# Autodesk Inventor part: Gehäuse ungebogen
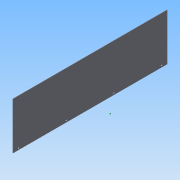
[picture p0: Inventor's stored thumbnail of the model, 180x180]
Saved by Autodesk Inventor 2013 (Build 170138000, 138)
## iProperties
Created: 2013-01
Part Number: Gehäuse ungebogen
Material: Allgemein
Document SubType Name: Modeling
Designer: Dan
Density: 1 g/cm^3
Author: Dan
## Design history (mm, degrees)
sketch "Skizze1"
  geometry: 1 further point
sketch "Skizze2"
  geometry: L1 (162.847, 43.02)-(-282.193, 43.02); L2 (-282.193, 43.02)-(-282.193, 179.02); L3 (-282.193, 179.02)-(162.847, 179.02); L4 (162.847, 179.02)-(162.847, 43.02); 1 further point
  constraints: 8 end point, 2 parallel, 1 horizontal, 1 perpendicular
  dimensions: "d0" = 445.04 distance of L2.end L3.end; "d2" = 136 distance of L1.end L2.end
extrude "Extrusion1" new body sketch "Skizze2" distance "d3" = 1; taper "d4" = 0 deg
hole "Bohrung1" diameter "d7" = 3.4; stored, may be unused: countersink angle "d11" = 90 deg, drill point angle "d13" = 118 deg; dims "d5" = 5, "d6" = 16.06, "d8" = 6, "d9" = 4, "d10" = 2, "d12" = 8
pattern_linear "Rechteckige Anordnung1" dims "d16" = 137.64
node "Volumenkörper1"
